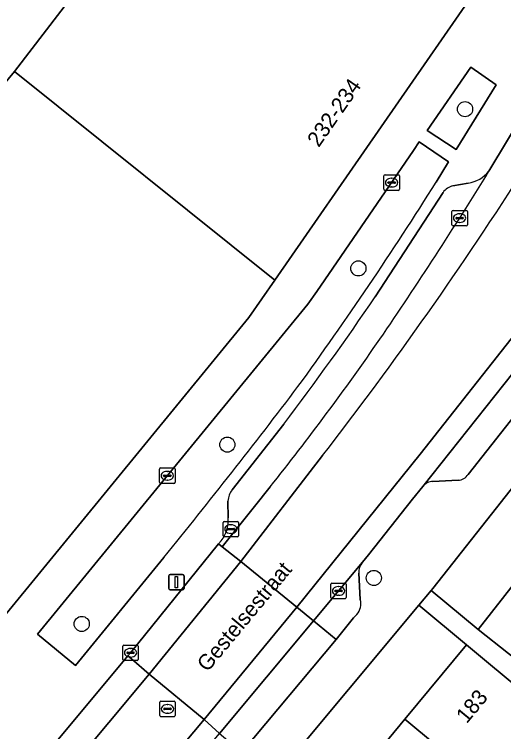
# Model space of a CAD drawing. Extents: x 160157 to 160921, y 381516 to 382045.
# Drawn here: x 160588.48 to 160620.07, y 381800.21 to 381846.52 of the extents above; entities that cross this region are included whole.
import ezdxf

# ---------------------------------------------------------------- set-up
doc = ezdxf.new("R2010")
doc.units = 0
for name, color, linetype in [('IMGEO_Berm_groen', 7, 'Continuous'), ('IMGEO_Boom', 7, 'Continuous'), ('IMGEO_Erf', 7, 'Continuous'), ('IMGEO_Kolk', 7, 'Continuous'), ('IMGEO_Lichtmast', 7, 'Continuous'), ('IMGEO_Openbare_ruimte_label', 7, 'Continuous'), ('IMGEO_Pand', 7, 'Continuous'), ('IMGEO_Pand_nummerreeks', 7, 'Continuous'), ('IMGEO_Parkeervlak_open', 7, 'Continuous'), ('IMGEO_Rijbaan_lokaal_gesloten', 7, 'Continuous'), ('IMGEO_Rijbaan_lokaal_open', 7, 'Continuous'), ('IMGEO_Rioolput', 7, 'Continuous'), ('IMGEO_Verkeerseiland_groen', 7, 'Continuous'), ('IMGEO_Voetpad_open', 7, 'Continuous')]:
    doc.layers.add(name, color=color, linetype=linetype)

msp = doc.modelspace()

# ---------------------------------------------------------------- linework, layer by layer
at = {"layer": 'IMGEO_Berm_groen'}
msp.add_lwpolyline([(160615.718, 381835.697), (160616.522, 381837.008), (160614.62, 381838.283), (160614.248, 381837.743), (160608.009, 381828.621), (160607.432, 381827.822), (160589.981, 381806.513), (160592.434, 381804.495), (160598.131, 381811.461)], dxfattribs=at)
for centre, radius, start, end in [((160415.33, 381961.531), 236.621, 324.01295, 327.87312), ((160294.102, 382059.086), 392.112, 320.83802, 322.88745)]:
    msp.add_arc(centre, radius, start, end, dxfattribs=at)
at = {"layer": 'IMGEO_Boom'}
for centre in [(160617.581, 381840.398), (160610.691, 381830.122), (160602.232, 381818.745), (160611.694, 381810.136), (160592.83, 381807.168)]:
    msp.add_circle(centre, 0.489, dxfattribs=at)
at = {"layer": 'IMGEO_Erf'}
msp.add_lwpolyline([(160644.987, 381846.807), (160615.493, 381809.458), (160615.388, 381809.332), (160618.417, 381806.806), (160623.586, 381813.39), (160627.35, 381818.185), (160630.989, 381822.82), (160634.598, 381827.418), (160638.269, 381832.094)], dxfattribs=at)
msp.add_lwpolyline([(160613.699, 381801.016), (160617.678, 381805.815), (160614.597, 381808.384), (160600.981, 381792.054), (160604.113, 381789.456), (160607.145, 381793.112), (160610.355, 381796.984)], close=True, dxfattribs=at)
at = {"layer": 'IMGEO_Kolk'}
for p, q in [((160612.338, 381835.236), (160612.338, 381836.088)), ((160612.413, 381836.162), (160613.265, 381836.162)), ((160613.339, 381836.088), (160613.339, 381835.236)), ((160612.597, 381835.656), (160612.597, 381835.668)), ((160613.035, 381835.619), (160612.637, 381835.619)), ((160612.64, 381835.705), (160613.038, 381835.705)), ((160612.826, 381835.942), (160612.851, 381835.942)), ((160613.081, 381835.668), (160613.081, 381835.656)), ((160613.265, 381835.162), (160612.413, 381835.162)), ((160612.849, 381835.382), (160612.824, 381835.382)), ((160616.727, 381832.943), (160616.727, 381833.795)), ((160616.802, 381833.869), (160617.654, 381833.869)), ((160617.728, 381833.795), (160617.728, 381832.943)), ((160616.986, 381833.363), (160616.986, 381833.375)), ((160617.424, 381833.326), (160617.026, 381833.326)), ((160617.029, 381833.412), (160617.427, 381833.412)), ((160617.215, 381833.649), (160617.24, 381833.649)), ((160617.47, 381833.375), (160617.47, 381833.363)), ((160617.654, 381832.869), (160616.802, 381832.869)), ((160617.238, 381833.089), (160617.213, 381833.089)), ((160597.853, 381816.312), (160597.853, 381817.164)), ((160597.928, 381817.238), (160598.78, 381817.238)), ((160598.854, 381817.164), (160598.854, 381816.312)), ((160598.112, 381816.732), (160598.112, 381816.744)), ((160598.55, 381816.695), (160598.152, 381816.695)), ((160598.155, 381816.781), (160598.553, 381816.781)), ((160598.341, 381817.018), (160598.366, 381817.018)), ((160598.596, 381816.744), (160598.596, 381816.732)), ((160598.78, 381816.238), (160597.928, 381816.238)), ((160598.364, 381816.458), (160598.339, 381816.458)), ((160602.034, 381813.792), (160602.886, 381813.792)), ((160601.959, 381812.866), (160601.959, 381813.718)), ((160602.261, 381813.335), (160602.659, 381813.335)), ((160602.447, 381813.572), (160602.472, 381813.572)), ((160602.96, 381813.718), (160602.96, 381812.866)), ((160602.218, 381813.286), (160602.218, 381813.298)), ((160602.656, 381813.249), (160602.258, 381813.249)), ((160602.47, 381813.012), (160602.445, 381813.012)), ((160602.702, 381813.298), (160602.702, 381813.286)), ((160602.886, 381812.792), (160602.034, 381812.792)), ((160608.912, 381808.874), (160608.912, 381809.726)), ((160608.987, 381809.8), (160609.839, 381809.8)), ((160609.913, 381809.726), (160609.913, 381808.874)), ((160609.171, 381809.294), (160609.171, 381809.306)), ((160609.609, 381809.257), (160609.211, 381809.257)), ((160609.214, 381809.343), (160609.612, 381809.343)), ((160609.4, 381809.58), (160609.425, 381809.58)), ((160609.655, 381809.306), (160609.655, 381809.294)), ((160609.839, 381808.8), (160608.987, 381808.8)), ((160609.423, 381809.02), (160609.398, 381809.02)), ((160595.482, 381804.879), (160595.482, 381805.731)), ((160595.557, 381805.805), (160596.409, 381805.805)), ((160595.97, 381805.585), (160595.995, 381805.585)), ((160596.483, 381805.731), (160596.483, 381804.879)), ((160595.741, 381805.299), (160595.741, 381805.311)), ((160596.179, 381805.262), (160595.781, 381805.262)), ((160595.784, 381805.348), (160596.182, 381805.348)), ((160595.993, 381805.025), (160595.968, 381805.025)), ((160596.225, 381805.311), (160596.225, 381805.299)), ((160596.409, 381804.805), (160595.557, 381804.805))]:
    msp.add_line(p, q, dxfattribs=at)
for points in [[(160612.338, 381835.236), (160612.338, 381836.088)], [(160612.413, 381836.162), (160613.265, 381836.162)], [(160613.339, 381836.088), (160613.339, 381835.236)], [(160613.265, 381835.162), (160612.413, 381835.162)], [(160616.727, 381832.943), (160616.727, 381833.795)], [(160616.802, 381833.869), (160617.654, 381833.869)], [(160617.728, 381833.795), (160617.728, 381832.943)], [(160617.654, 381832.869), (160616.802, 381832.869)], [(160597.853, 381816.312), (160597.853, 381817.164)], [(160597.928, 381817.238), (160598.78, 381817.238)], [(160598.854, 381817.164), (160598.854, 381816.312)], [(160598.78, 381816.238), (160597.928, 381816.238)], [(160602.034, 381813.792), (160602.886, 381813.792)], [(160601.959, 381812.866), (160601.959, 381813.718)], [(160602.96, 381813.718), (160602.96, 381812.866)], [(160602.886, 381812.792), (160602.034, 381812.792)], [(160608.912, 381808.874), (160608.912, 381809.726)], [(160608.987, 381809.8), (160609.839, 381809.8)], [(160609.913, 381809.726), (160609.913, 381808.874)], [(160609.839, 381808.8), (160608.987, 381808.8)], [(160595.482, 381804.879), (160595.482, 381805.731)], [(160595.557, 381805.805), (160596.409, 381805.805)], [(160596.483, 381805.731), (160596.483, 381804.879)], [(160596.409, 381804.805), (160595.557, 381804.805)]]:
    msp.add_lwpolyline(points, dxfattribs=at)
for centre, radius, start, end in [((160612.415, 381836.086), 0.0765, 91.552, 178.448), ((160612.415, 381836.086), 0.0765, 91.552, 178.448), ((160613.263, 381836.086), 0.0765, 1.552, 88.448), ((160613.263, 381836.086), 0.0765, 1.552, 88.448), ((160612.637, 381835.665), 0.0403, 85.8775, 175.7526), ((160612.634, 381835.655), 0.0366, 178.938, 274.7102), ((160613.038, 381835.662), 0.043, 264.8664, 352.4533), ((160613.042, 381835.667), 0.0386, 1.7309, 96.639), ((160612.415, 381835.238), 0.0765, 181.552, 268.448), ((160612.415, 381835.238), 0.0765, 181.552, 268.448), ((160613.263, 381835.238), 0.0765, 271.552, 358.448), ((160613.263, 381835.238), 0.0765, 271.552, 358.448), ((160616.804, 381833.793), 0.0765, 91.552, 178.448), ((160616.804, 381833.793), 0.0765, 91.552, 178.448), ((160617.652, 381833.793), 0.0765, 1.552, 88.448), ((160617.652, 381833.793), 0.0765, 1.552, 88.448), ((160617.026, 381833.372), 0.0403, 85.8775, 175.7526), ((160617.023, 381833.362), 0.0366, 178.938, 274.7102), ((160617.427, 381833.369), 0.043, 264.8664, 352.4533), ((160617.431, 381833.374), 0.0386, 1.7309, 96.639), ((160616.804, 381832.945), 0.0765, 181.552, 268.448), ((160616.804, 381832.945), 0.0765, 181.552, 268.448), ((160617.652, 381832.945), 0.0765, 271.552, 358.448), ((160617.652, 381832.945), 0.0765, 271.552, 358.448), ((160597.93, 381817.162), 0.0765, 91.552, 178.448), ((160597.93, 381817.162), 0.0765, 91.552, 178.448), ((160598.778, 381817.162), 0.0765, 1.552, 88.448), ((160598.778, 381817.162), 0.0765, 1.552, 88.448), ((160598.152, 381816.741), 0.0403, 85.8775, 175.7526), ((160598.149, 381816.731), 0.0366, 178.938, 274.7102), ((160598.553, 381816.738), 0.043, 264.8664, 352.4533), ((160598.557, 381816.743), 0.0386, 1.7309, 96.639), ((160597.93, 381816.314), 0.0765, 181.552, 268.448), ((160597.93, 381816.314), 0.0765, 181.552, 268.448), ((160598.778, 381816.314), 0.0765, 271.552, 358.448), ((160598.778, 381816.314), 0.0765, 271.552, 358.448), ((160602.036, 381813.716), 0.0765, 91.552, 178.448), ((160602.036, 381813.716), 0.0765, 91.552, 178.448), ((160602.884, 381813.716), 0.0765, 1.552, 88.448), ((160602.884, 381813.716), 0.0765, 1.552, 88.448), ((160602.258, 381813.295), 0.0403, 85.8775, 175.7526), ((160602.663, 381813.297), 0.0386, 1.7309, 96.639), ((160602.036, 381812.868), 0.0765, 181.552, 268.448), ((160602.036, 381812.868), 0.0765, 181.552, 268.448), ((160602.255, 381813.285), 0.0366, 178.938, 274.7102), ((160602.659, 381813.292), 0.043, 264.8664, 352.4533), ((160602.884, 381812.868), 0.0765, 271.552, 358.448), ((160602.884, 381812.868), 0.0765, 271.552, 358.448), ((160608.989, 381809.724), 0.0765, 91.552, 178.448), ((160608.989, 381809.724), 0.0765, 91.552, 178.448), ((160609.837, 381809.724), 0.0765, 1.552, 88.448), ((160609.837, 381809.724), 0.0765, 1.552, 88.448), ((160609.211, 381809.303), 0.0403, 85.8775, 175.7526), ((160609.208, 381809.293), 0.0366, 178.938, 274.7102), ((160609.612, 381809.3), 0.043, 264.8664, 352.4533), ((160609.616, 381809.305), 0.0386, 1.7309, 96.639), ((160608.989, 381808.876), 0.0765, 181.552, 268.448), ((160608.989, 381808.876), 0.0765, 181.552, 268.448), ((160609.837, 381808.876), 0.0765, 271.552, 358.448), ((160609.837, 381808.876), 0.0765, 271.552, 358.448), ((160595.559, 381805.729), 0.0765, 91.552, 178.448), ((160595.559, 381805.729), 0.0765, 91.552, 178.448), ((160596.407, 381805.729), 0.0765, 1.552, 88.448), ((160596.407, 381805.729), 0.0765, 1.552, 88.448), ((160595.781, 381805.308), 0.0403, 85.8775, 175.7526), ((160595.778, 381805.298), 0.0366, 178.938, 274.7102), ((160596.182, 381805.305), 0.043, 264.8664, 352.4533), ((160596.186, 381805.31), 0.0386, 1.7309, 96.639), ((160595.559, 381804.881), 0.0765, 181.552, 268.448), ((160595.559, 381804.881), 0.0765, 181.552, 268.448), ((160596.407, 381804.881), 0.0765, 271.552, 358.448), ((160596.407, 381804.881), 0.0765, 271.552, 358.448)]:
    msp.add_arc(centre, radius, start, end, dxfattribs=at)
for centre, major_axis, ratio, start_param, end_param in [((160612.825, 381835.662), (-0.387, 0.002), 0.722429, 4.712389, 7.853982), ((160612.85, 381835.662), (-0.39, 0.002), 0.717154, 1.570796, 4.712389), ((160617.214, 381833.369), (-0.387, 0.002), 0.722429, 4.712389, 7.853982), ((160617.239, 381833.369), (-0.39, 0.002), 0.717154, 1.570796, 4.712389), ((160598.34, 381816.738), (-0.387, 0.002), 0.722429, 4.712389, 7.853982), ((160598.365, 381816.738), (-0.39, 0.002), 0.717154, 1.570796, 4.712389), ((160602.446, 381813.292), (-0.387, 0.002), 0.722429, 4.712389, 7.853982), ((160602.471, 381813.292), (-0.39, 0.002), 0.717154, 1.570796, 4.712389), ((160609.399, 381809.3), (-0.387, 0.002), 0.722429, 4.712389, 7.853982), ((160609.424, 381809.3), (-0.39, 0.002), 0.717154, 1.570796, 4.712389), ((160595.969, 381805.305), (-0.387, 0.002), 0.722429, 4.712389, 7.853982), ((160595.994, 381805.305), (-0.39, 0.002), 0.717154, 1.570796, 4.712389)]:
    msp.add_ellipse(centre, major_axis=major_axis, ratio=ratio, start_param=start_param, end_param=end_param, dxfattribs=at)
at = {"layer": 'IMGEO_Lichtmast'}
for p, q in [((160598.447, 381809.465), (160598.447, 381810.265)), ((160598.447, 381810.265), (160598.447, 381809.465)), ((160598.547, 381810.365), (160599.337, 381810.365)), ((160599.337, 381810.365), (160598.547, 381810.365)), ((160599.437, 381810.265), (160599.437, 381809.465)), ((160599.437, 381809.465), (160599.437, 381810.265)), ((160599.337, 381809.365), (160598.547, 381809.365)), ((160598.547, 381809.365), (160599.337, 381809.365))]:
    msp.add_line(p, q, dxfattribs=at)
msp.add_lwpolyline([(160598.867, 381810.24), (160599.017, 381810.24), (160599.017, 381809.49), (160598.867, 381809.49), (160598.867, 381810.24)], dxfattribs=at)
for centre, start, end in [((160598.547, 381810.265), 90, 180), ((160598.547, 381810.265), 90, 180), ((160599.337, 381810.265), 0, 90), ((160599.337, 381810.265), 360, 90), ((160598.547, 381809.465), 180, 270), ((160598.547, 381809.465), 180, 270), ((160599.337, 381809.465), 270, 0), ((160599.337, 381809.465), 270, 0)]:
    msp.add_arc(centre, 0.1, start, end, dxfattribs=at)
at = {"layer": 'IMGEO_Pand'}
for points in [[(160588.491, 381842.842), (160601.155, 381859.363), (160601.388, 381859.766), (160601.281, 381859.829), (160603.363, 381863.888), (160600.911, 381865.899), (160597.132, 381861.291), (160586.581, 381869.944), (160571.764, 381851.877), (160568.593, 381848.01), (160573.076, 381844.333), (160577.258, 381840.904), (160572.943, 381835.644), (160578.657, 381830.957)], [(160619.02, 381849.186), (160601.155, 381859.363), (160588.491, 381842.842), (160605.3, 381829.37)], [(160623.586, 381813.39), (160618.417, 381806.806), (160622.35, 381803.719), (160624.886, 381801.729), (160628.579, 381806.423), (160631.654, 381804.003), (160633.139, 381805.89)], [(160613.699, 381801.016), (160624.054, 381792.414), (160626.058, 381794.831), (160621.866, 381798.306), (160623.85, 381800.698), (160621.528, 381802.623), (160617.678, 381805.815)], [(160616.457, 381791.914), (160618.151, 381793.957), (160622.407, 381790.428), (160624.054, 381792.414), (160613.699, 381801.016), (160610.355, 381796.984)]]:
    msp.add_lwpolyline(points, close=True, dxfattribs=at)
msp.add_lwpolyline([(160544.205, 381808.84), (160545.119, 381808.768), (160545.043, 381807.398), (160552.339, 381806.92), (160552.423, 381807.918), (160565.264, 381807.052), (160573.135, 381800.579), (160574.832, 381802.642), (160577.89, 381806.362), (160573.653, 381809.843), (160578.412, 381815.643), (160587.941, 381807.827), (160603.624, 381826.949), (160605.3, 381829.37), (160588.491, 381842.842), (160578.657, 381830.957), (160571.054, 381821.687), (160553.382, 381822.841), (160546.076, 381823.333), (160545.997, 381821.984), (160545.068, 381822.034)], dxfattribs=at)
at = {"layer": 'IMGEO_Parkeervlak_open'}
for points in [[(160638.255, 381846.511), (160634.363, 381840.886), (160620.664, 381823.358), (160614.85, 381816.044)], [(160617.781, 381816.821), (160629.501, 381831.69), (160634.532, 381838.199)], [(160617.784, 381835.627), (160616.796, 381835.451)], [(160616.157, 381835.031), (160611.784, 381828.294)], [(160605.877, 381820.072), (160602.546, 381815.83)], [(160615.505, 381816.374), (160617.125, 381816.444)], [(160601.84, 381812.537), (160601.661, 381812.342), (160601.896, 381812.152), (160603.985, 381814.756), (160605.004, 381816.026)], [(160602.27, 381815.105), (160602.289, 381814.009)], [(160610.953, 381811.147), (160607.794, 381807.361), (160609.261, 381806.17), (160610.386, 381807.561), (160610.601, 381807.783)], [(160610.815, 381808.75), (160610.717, 381810.451)]]:
    msp.add_lwpolyline(points, dxfattribs=at)
msp.add_lwpolyline([(160607.794, 381807.361), (160601.731, 381800.097), (160603.167, 381798.883), (160609.261, 381806.17)], close=True, dxfattribs=at)
for centre, radius, start, end in [((160379.037, 381984.723), 282.213, 325.66593, 328.29116), ((160617.438, 381837.792), 2.192, 279.0896, 320.2896), ((160617.08, 381834.323), 1.163, 104.1286, 142.5034), ((160450.297, 381938.079), 195.271, 322.81965, 325.79052), ((160467.342, 381925.664), 175.987, 321.4651, 325.32828), ((160617.066, 381817.307), 0.865, 273.9448, 325.8268), ((160615.557, 381815.456), 0.92, 93.2476, 140.2319), ((160603.552, 381815.032), 1.284, 141.5765, 176.7409), ((160600.055, 381813.886), 2.237, 322.9195, 3.1542), ((160611.766, 381810.483), 1.05, 140.7815, 181.7569), ((160609.777, 381808.472), 1.074, 320.0729, 14.9699)]:
    msp.add_arc(centre, radius, start, end, dxfattribs=at)
at = {"layer": 'IMGEO_Rijbaan_lokaal_gesloten'}
msp.add_lwpolyline([(160634.363, 381840.886), (160638.255, 381846.511), (160638.774, 381847.331), (160642.317, 381853.209), (160643.662, 381855.505), (160641.866, 381856.528), (160641.849, 381856.501), (160640.924, 381854.723), (160633.663, 381842.9), (160631.565, 381839.849), (160629.021, 381836.504), (160622.418, 381827.913), (160614.68, 381818.128), (160606.724, 381808.255), (160607.794, 381807.361), (160610.953, 381811.147), (160611.342, 381811.635), (160614.195, 381815.222), (160614.85, 381816.044), (160620.664, 381823.358)], close=True, dxfattribs=at)
for points in [[(160621.517, 381836.714), (160626.614, 381844.846), (160624.799, 381845.862), (160623.4, 381843.528), (160621.588, 381840.503), (160619.124, 381836.391)], [(160605.004, 381816.026), (160603.985, 381814.756), (160601.896, 381812.152), (160603.102, 381811.204), (160608.386, 381818.048)], [(160556.164, 381754.68), (160558.112, 381757.129), (160560.755, 381760.365), (160581.539, 381785.212), (160597.19, 381803.934), (160596.045, 381804.906), (160595.807, 381805.107), (160595.401, 381804.621), (160589.126, 381797.112), (160588.465, 381796.32), (160588.699, 381796.124), (160587.352, 381794.513), (160562.011, 381764.214), (160561.758, 381763.877), (160556.569, 381757.556), (160552.708, 381752.669), (160550.722, 381750)], [(160559.501, 381749.238), (160560.113, 381750), (160567.175, 381758.693), (160571.401, 381763.753), (160601.731, 381800.097), (160600.729, 381800.991), (160582.713, 381779.526), (160568.843, 381763.002), (160559.601, 381751.709)]]:
    msp.add_lwpolyline(points, dxfattribs=at)
for centre, radius, start, end in [((160413.69, 381968.963), 246.337, 322.21966, 327.52975), ((160379.037, 381984.723), 282.213, 325.66593, 328.29116), ((160467.342, 381925.664), 175.987, 321.4651, 325.32828)]:
    msp.add_arc(centre, radius, start, end, dxfattribs=at)
at = {"layer": 'IMGEO_Rijbaan_lokaal_open'}
for points in [[(160608.386, 381818.048), (160603.102, 381811.204), (160606.724, 381808.255), (160614.68, 381818.128), (160622.418, 381827.913), (160629.021, 381836.504), (160631.565, 381839.849), (160633.663, 381842.9), (160640.924, 381854.723), (160641.849, 381856.501)], [(160568.843, 381763.002), (160582.713, 381779.526), (160600.729, 381800.991), (160597.19, 381803.934), (160581.539, 381785.212), (160560.755, 381760.365), (160558.112, 381757.129), (160556.164, 381754.68)]]:
    msp.add_lwpolyline(points, dxfattribs=at)
for points in [[(160603.102, 381811.204), (160601.896, 381812.152), (160601.661, 381812.342), (160595.983, 381805.304), (160595.807, 381805.107), (160596.045, 381804.906), (160597.19, 381803.934)], [(160606.724, 381808.255), (160603.102, 381811.204), (160597.19, 381803.934), (160600.729, 381800.991)], [(160607.794, 381807.361), (160606.724, 381808.255), (160600.729, 381800.991), (160601.731, 381800.097)]]:
    msp.add_lwpolyline(points, close=True, dxfattribs=at)
msp.add_arc((160413.69, 381968.963), 246.337, 322.21966, 327.52975, dxfattribs=at)
at = {"layer": 'IMGEO_Rioolput'}
for p, q in [((160597.865, 381801.256), (160597.865, 381802.108)), ((160597.94, 381802.182), (160598.792, 381802.182)), ((160598.353, 381801.962), (160598.378, 381801.962)), ((160598.866, 381802.108), (160598.866, 381801.256)), ((160598.124, 381801.676), (160598.124, 381801.688)), ((160598.562, 381801.639), (160598.164, 381801.639)), ((160598.167, 381801.725), (160598.565, 381801.725)), ((160598.376, 381801.402), (160598.351, 381801.402)), ((160598.608, 381801.688), (160598.608, 381801.676)), ((160598.792, 381801.182), (160597.94, 381801.182))]:
    msp.add_line(p, q, dxfattribs=at)
for points in [[(160597.865, 381801.256), (160597.865, 381802.108)], [(160597.94, 381802.182), (160598.792, 381802.182)], [(160598.866, 381802.108), (160598.866, 381801.256)], [(160598.792, 381801.182), (160597.94, 381801.182)]]:
    msp.add_lwpolyline(points, dxfattribs=at)
for centre, radius, start, end in [((160597.942, 381802.106), 0.0765, 91.552, 178.448), ((160597.942, 381802.106), 0.0765, 91.552, 178.448), ((160598.79, 381802.106), 0.0765, 1.552, 88.448), ((160598.79, 381802.106), 0.0765, 1.552, 88.448), ((160598.164, 381801.685), 0.0403, 85.8775, 175.7526), ((160598.161, 381801.675), 0.0366, 178.938, 274.7102), ((160598.565, 381801.682), 0.043, 264.8664, 352.4533), ((160598.569, 381801.687), 0.0386, 1.7309, 96.639), ((160597.942, 381801.258), 0.0765, 181.552, 268.448), ((160597.942, 381801.258), 0.0765, 181.552, 268.448), ((160598.79, 381801.258), 0.0765, 271.552, 358.448), ((160598.79, 381801.258), 0.0765, 271.552, 358.448)]:
    msp.add_arc(centre, radius, start, end, dxfattribs=at)
for centre, major_axis, ratio, start_param, end_param in [((160598.352, 381801.682), (-0.387, 0.002), 0.722429, 4.712389, 7.853982), ((160598.377, 381801.682), (-0.39, 0.002), 0.717154, 1.570796, 4.712389)]:
    msp.add_ellipse(centre, major_axis=major_axis, ratio=ratio, start_param=start_param, end_param=end_param, dxfattribs=at)
at = {"layer": 'IMGEO_Verkeerseiland_groen'}
msp.add_lwpolyline([(160619.586, 381841.973), (160617.943, 381843.111), (160615.138, 381839.035), (160617.016, 381837.804)], close=True, dxfattribs=at)
at = {"layer": 'IMGEO_Voetpad_open'}
for points in [[(160636.204, 381887.952), (160632.445, 381887.634), (160629.203, 381881.464), (160628.641, 381880.394), (160617.475, 381859.142), (160622.595, 381856.109), (160622.949, 381854.734), (160626.183, 381852.944), (160622.758, 381846.92), (160619.505, 381848.899), (160619.02, 381849.186), (160605.3, 381829.37), (160603.624, 381826.949), (160587.941, 381807.827), (160580.593, 381798.887)], [(160614.597, 381808.384), (160615.388, 381809.332), (160615.493, 381809.458), (160644.987, 381846.807), (160647.699, 381851.584), (160653.212, 381861.298), (160654.415, 381863.144), (160655.188, 381864.027), (160655.682, 381864.592), (160657.082, 381865.462), (160658.571, 381866.17), (160660.296, 381866.624), (160662.715, 381866.57), (160664.857, 381866.115), (160653.156, 381872.105), (160648.639, 381864.194), (160643.955, 381855.993), (160643.662, 381855.505), (160642.317, 381853.209), (160638.774, 381847.331), (160638.255, 381846.511)], [(160619.124, 381836.391), (160621.588, 381840.503), (160623.4, 381843.528), (160624.799, 381845.862), (160624.978, 381846.161)], [(160589.981, 381806.513), (160607.432, 381827.822), (160608.009, 381828.621), (160614.248, 381837.743), (160614.62, 381838.283), (160616.522, 381837.008), (160615.718, 381835.697)], [(160634.532, 381838.199), (160629.501, 381831.69), (160617.781, 381816.821)], [(160616.796, 381835.451), (160617.784, 381835.627)], [(160611.784, 381828.294), (160616.157, 381835.031)], [(160602.546, 381815.83), (160605.877, 381820.072)], [(160617.125, 381816.444), (160615.505, 381816.374)], [(160614.85, 381816.044), (160614.195, 381815.222), (160611.342, 381811.635), (160610.953, 381811.147)], [(160602.289, 381814.009), (160602.27, 381815.105)], [(160595.401, 381804.621), (160595.807, 381805.107), (160595.983, 381805.304), (160601.661, 381812.342), (160601.84, 381812.537)], [(160598.131, 381811.461), (160592.434, 381804.495), (160589.981, 381806.513)], [(160610.717, 381810.451), (160610.815, 381808.75)], [(160632.65, 381795.49), (160624.886, 381801.729), (160622.35, 381803.719), (160618.417, 381806.806), (160615.388, 381809.332), (160614.597, 381808.384), (160617.678, 381805.815), (160621.528, 381802.623), (160623.85, 381800.698), (160637.708, 381789.314)], [(160560.449, 381748.035), (160561.169, 381743.908), (160564.062, 381747.78), (160565.914, 381750), (160580.313, 381767.268), (160580.96, 381768.044), (160600.191, 381791.107), (160600.981, 381792.054), (160614.597, 381808.384)], [(160610.601, 381807.783), (160610.386, 381807.561), (160609.261, 381806.17), (160603.167, 381798.883), (160599.457, 381794.39), (160587.813, 381780.546)], [(160588.465, 381796.32), (160589.126, 381797.112), (160595.401, 381804.621)]]:
    msp.add_lwpolyline(points, dxfattribs=at)
msp.add_lwpolyline([(160615.138, 381839.035), (160617.943, 381843.111), (160619.586, 381841.973), (160617.016, 381837.804)], close=True, dxfattribs=at)
for centre, radius, start, end in [((160617.438, 381837.792), 2.192, 279.0896, 320.2896), ((160415.33, 381961.531), 236.621, 324.01295, 327.87312), ((160617.08, 381834.323), 1.163, 104.1286, 142.5034), ((160450.297, 381938.079), 195.271, 322.81965, 325.79052), ((160294.102, 382059.086), 392.112, 320.83802, 322.88745), ((160617.066, 381817.307), 0.865, 273.9448, 325.8268), ((160615.557, 381815.456), 0.92, 93.2476, 140.2319), ((160603.552, 381815.032), 1.284, 141.5765, 176.7409), ((160600.055, 381813.886), 2.237, 322.9195, 3.1542), ((160611.766, 381810.483), 1.05, 140.7815, 181.7569), ((160609.777, 381808.472), 1.074, 320.0729, 14.9699)]:
    msp.add_arc(centre, radius, start, end, dxfattribs=at)

# ---------------------------------------------------------------- texts
at = {"layer": 'IMGEO_Openbare_ruimte_label'}
msp.add_text('Gestelsestraat', height=1, rotation=50.2751, dxfattribs=at).set_placement((160600.95, 381804.017))
at = {"layer": 'IMGEO_Pand_nummerreeks'}
for s, rotation, p in [('232-234', 55.3024, (160608.133, 381837.889)), ('183', 50.3342, (160617.685, 381800.686))]:
    msp.add_text(s, height=1, rotation=rotation, dxfattribs=at).set_placement(p)

doc.saveas('drawing.dxf')
